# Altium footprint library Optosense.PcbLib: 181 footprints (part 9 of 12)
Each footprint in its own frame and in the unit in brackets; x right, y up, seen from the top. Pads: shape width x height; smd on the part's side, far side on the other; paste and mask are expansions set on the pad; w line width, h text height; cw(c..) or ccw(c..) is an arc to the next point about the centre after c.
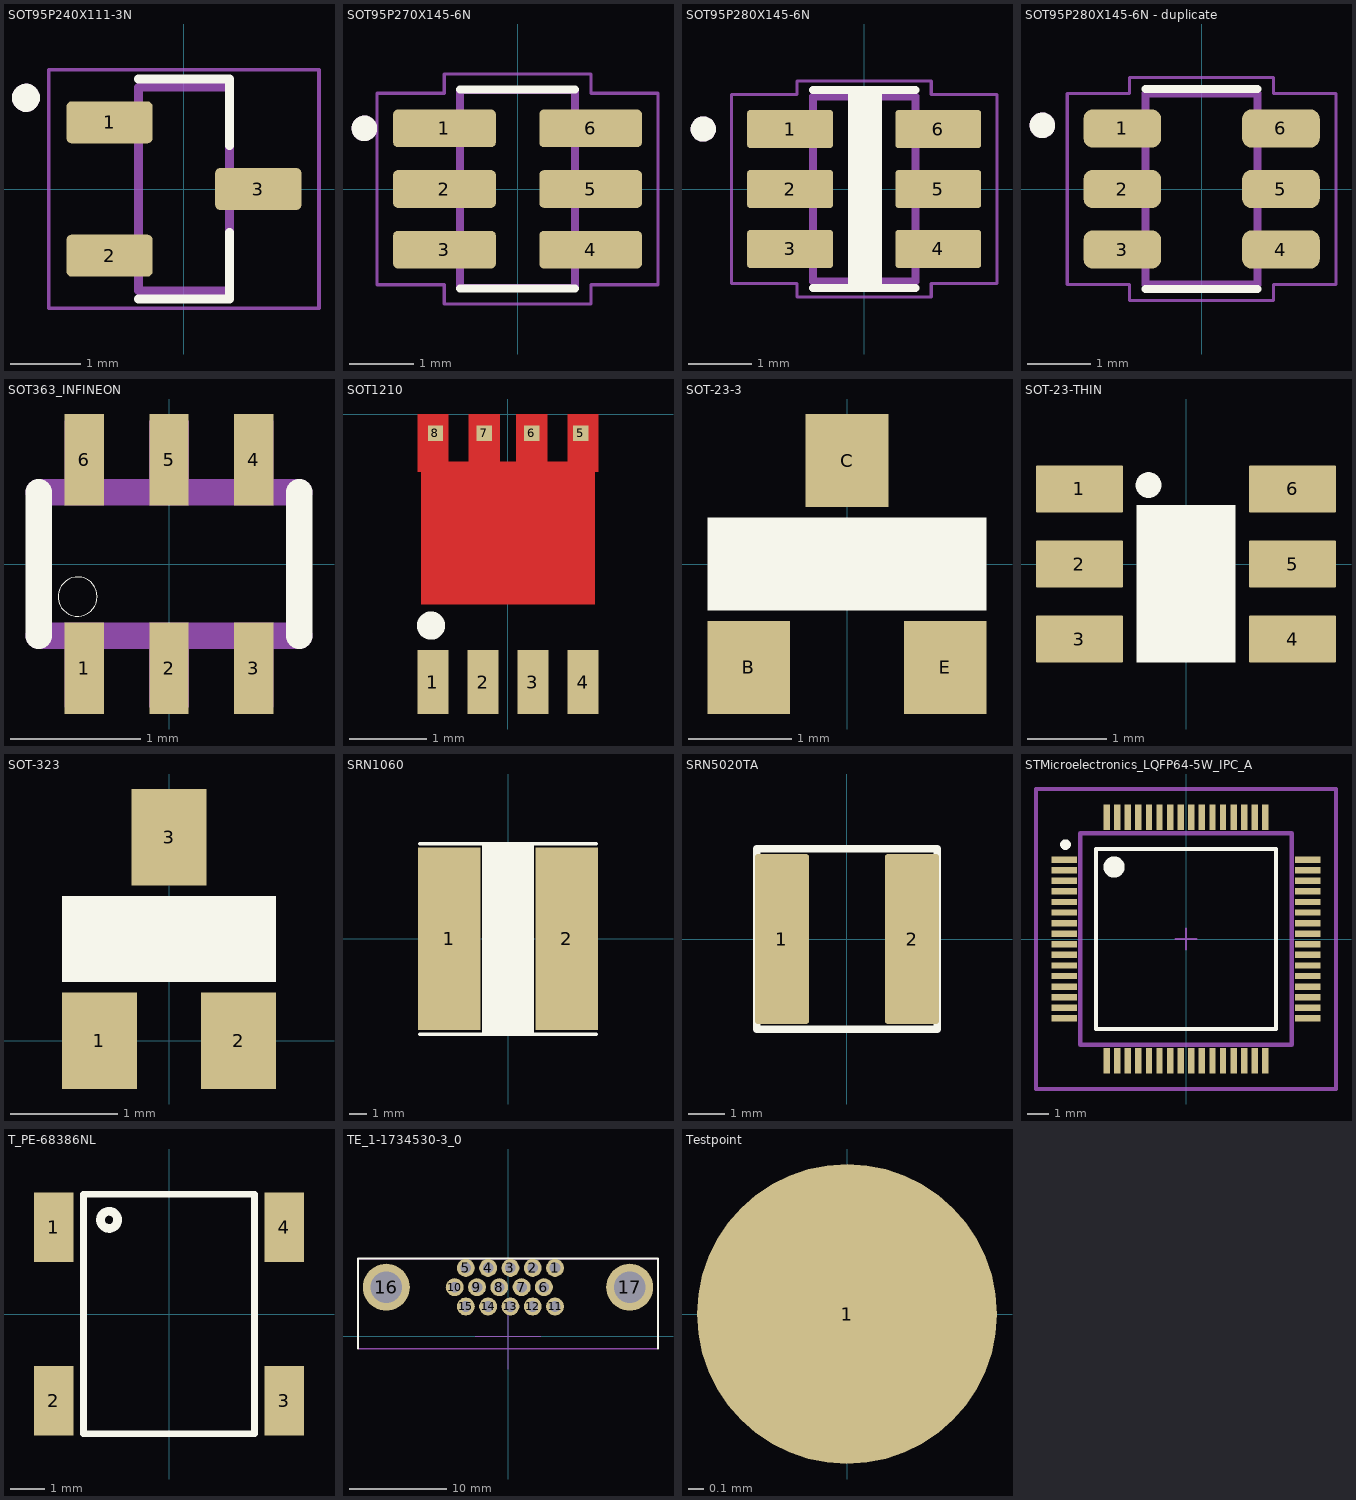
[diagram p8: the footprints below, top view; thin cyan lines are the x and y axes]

## SOT95P240X111-3N [mm]
pads (3):
  rrect25% 1.23x0.6 smd: 1(-1.06,0.95) 2(-1.06,-0.95) 3(1.06,0)
Top Overlay:
  circle w0.2: c-2.25,1.3 r0.1
  lines w0.127: -0.65,-1.57 0.65,-1.57 0.65,-0.62 ; -0.65,1.57 0.65,1.57 0.65,0.62
Mechanical 13:
  circle w0.2: c-2.25,1.3 r0.1
  lines w0.127: -0.65,-1.45 -0.65,1.45 0.65,1.45 0.65,-1.45 -0.65,-1.45
Mechanical 15:
  lines w0.05: -1.925,-1.7 1.925,-1.7 1.925,1.7 -1.925,1.7 -1.925,-1.7
3D body "step_temp.STEP": height 1.1, standoff 0, extent -1.15,-1.45 1.15,1.45

## SOT95P270X145-6N [mm]
pads (6):
  rrect25% 1.61x0.59 smd: 1(-1.145,0.95) 2(-1.145,0) 3(-1.145,-0.95) 4(1.145,-0.95) 5(1.145,0) 6(1.145,0.95)
Top Overlay:
  circle w0.2: c-2.4,0.95 r0.1
  lines w0.127: -0.9,-1.559 0.9,-1.559 ; -0.9,1.559 0.9,1.559
Mechanical 13:
  circle w0.2: c-2.4,0.95 r0.1
  lines w0.127: -0.9,-1.55 -0.9,1.55 0.9,1.55 0.9,-1.55 -0.9,-1.55
Mechanical 15:
  lines w0.05: -2.2,-1.5 -2.2,1.5 -1.15,1.5 -1.15,1.8 1.15,1.8 1.15,1.5 2.2,1.5 2.2,-1.5 1.15,-1.5 1.15,-1.8 -1.15,-1.8 -1.15,-1.5 -2.2,-1.5
3D body "USBLC6-2SC6Y--3DModel-STEP-56544.STEP": height 1.5, standoff 0.05, extent -1.43,-1.462 1.37,1.462

## SOT95P280X145-6N [mm]
pads (6):
  rrect15% 1.36x0.6 smd: 1(-1.175,0.95) 2(-1.175,0) 3(-1.175,-0.95) 4(1.175,-0.95) 5(1.175,0) 6(1.175,0.95)
Top Overlay:
  circle w0.2: c-2.55,0.95 r0.1
  rectangle: -0.254,-1.57 0.279,1.57
  lines w0.127: -0.813,-1.57 0.813,-1.57 ; -0.813,1.57 0.813,1.57
Mechanical 13:
  circle w0.2: c-2.55,0.95 r0.1
  lines w0.127: -0.813,-1.462 0.813,-1.462 0.813,1.462 -0.813,1.462 -0.813,-1.462
Mechanical 15:
  lines w0.05: -2.105,-1.5 -1.062,-1.5 -1.062,-1.713 1.062,-1.713 1.062,-1.5 2.105,-1.5 2.105,1.5 1.062,1.5 1.062,1.713 -1.062,1.713 -1.062,1.5 -2.105,1.5 -2.105,-1.5
3D body "USBLC6-2SC6Y--3DModel-STEP-56544.STEP": height 1.5, standoff 0.05, extent -1.4,-1.462 1.4,1.462

## SOT95P280X145-6N - duplicate [mm]
pads (6):
  rrect50% 1.22x0.6 smd: 1(-1.245,0.95) 2(-1.245,0) 3(-1.245,-0.95) 4(1.245,-0.95) 5(1.245,0) 6(1.245,0.95)
Top Overlay:
  circle w0.2: c-2.5,1 r0.1
  lines w0.127: -0.88,-1.57 0.88,-1.57 ; -0.88,1.57 0.88,1.57
Mechanical 13:
  circle w0.2: c-2.5,1 r0.1
  lines w0.127: -0.88,-1.5 0.88,-1.5 0.88,1.5 -0.88,1.5 -0.88,-1.5
Mechanical 15:
  lines w0.05: -2.11,-1.5 -2.11,1.5 -1.13,1.5 -1.13,1.75 1.13,1.75 1.13,1.5 2.11,1.5 2.11,-1.5 1.13,-1.5 1.13,-1.75 -1.13,-1.75 -1.13,-1.5 -2.11,-1.5

## SOT363_INFINEON [mm]
pads (6):
  rect 0.3x0.7 smd: 1(-0.65,-0.8) 2(0,-0.8) 3(0.65,-0.8) 4(0.65,0.8) 5(0,0.8) 6(-0.65,0.8)
Top Overlay:
  circle w0: c-0.7,-0.25 r0.15
  lines w0.203: -1,-0.55 -1,0.55 ; 1,-0.55 1,0.55
Mechanical 13:
  region: -0.5,0.6 -0.8,0.6 -0.8,1.1 -0.5,1.1
  region: 0.15,0.6 -0.15,0.6 -0.15,1.1 0.15,1.1
  region: 0.8,0.6 0.5,0.6 0.5,1.1 0.8,1.1
  region: 0.8,-1.1 0.5,-1.1 0.5,-0.6 0.8,-0.6
  region: 0.15,-1.1 -0.15,-1.1 -0.15,-0.6 0.15,-0.6
  region: -0.5,-1.1 -0.8,-1.1 -0.8,-0.6 -0.5,-0.6
  lines w0.203: -1,-0.55 1,-0.55 ; -1,0.55 1,0.55
3D body "User Library-sot363.STEP": height 1, standoff 0, extent -1.05,-1.15 1.05,1.15

## SOT1210 [mm]
pads (8):
  rect 0.4x0.83 smd: 1(-0.975,-3.485) 2(-0.325,-3.485) 3(0.325,-3.485) 4(0.975,-3.485)
  rect 0.2x0.2 smd: 5(0.944,-0.25) 6(0.309,-0.25) 7(-0.308,-0.25) 8(-0.943,-0.25)
Top Layer:
  region: -1.175,0 -1.175,-0.75 -1.125,-0.75 -1.125,-2.47 1.125,-2.47 1.125,-0.75 1.175,-0.75 1.175,0 0.775,0 0.775,-0.62 0.509,-0.62 0.509,0 0.109,0 0.109,-0.62 -0.109,-0.62 -0.109,0 -0.509,0 -0.509,-0.62 -0.775,-0.62 -0.775,0
Top Overlay:
  circle w0.254: c-1,-2.75 r0.056
Top Paste:
  region: -0.309,-1.91 -0.309,-2.42 -0.944,-2.42 -0.944,-1.91
  region: -1.125,0 -1.125,-0.75 -0.825,-0.75 -0.825,0
  region: -0.459,0 -0.459,-0.75 -0.159,-0.75 -0.159,0
  region: 0.159,0 0.159,-0.75 0.459,-0.75 0.459,0
  region: 1.125,0 1.125,-0.75 0.825,-0.75 0.825,0
  region: -0.309,-1.05 -0.309,-1.56 -0.944,-1.56 -0.944,-1.05
  region: 0.943,-1.05 0.943,-1.56 0.308,-1.56 0.308,-1.05
  region: 0.943,-1.91 0.943,-2.42 0.308,-2.42 0.308,-1.91
3D body "SOT1210.step": height 0.61, standoff -0.25, extent -1.638,-3.512 1.662,-0.212

## SOT-23-3 [mm]
height 1.025
pads (3):
  rect 0.8x0.9 smd: B(-0.95,-1) C(0,1) E(0.95,-1)
Top Overlay:
  rectangle: -1.35,-0.45 1.35,0.45
3D body "User Library-3-lead sot23-3.STEP": height 1, standoff -0.02, extent -1.46,-1.225 1.46,1.251

## SOT-23-THIN [mm]
height 1.1
pads (6):
  rrect5% 1.1x0.6 smd mask+0.07: 1(-1.35,0.95) 2(-1.35,0) 3(-1.35,-0.95) 4(1.35,-0.95) 5(1.35,0) 6(1.35,0.95)
Top Overlay:
  circle w0.254: c-0.475,1 r0.035
  rectangle: -0.625,-1.25 0.625,0.75
3D body "TPS54302DDCT.stp": height 1.1, standoff 0, extent -1.4,-1.45 1.4,1.45

## SOT-323 [mm]
height 1.1
pads (3):
  rect 0.7x0.9 smd: 1(-0.65,0) 2(0.65,0) 3(0,1.9)
Top Overlay:
  rectangle: -1,0.55 1,1.35
3D body "User Library-BC847BW.step": height 0.3, standoff -0.65, extent -1,-0.05 1,2.05

## Splitter [mm]
3D body "Splitter.step": height 26.51, standoff 0.6, extent -3.5,0 105.597,80

## SRN1060 [mm]
height 6
pads (2):
  rect 3.5x10.2 smd paste-5: 1(-3.3,0) 2(3.3,0)
Top Overlay:
  rectangle: -1.45,-5.35 1.45,5.325
  lines w0.2: -4.95,-5.35 4.95,-5.35 ; -4.95,5.325 4.95,5.325
Top Paste:
  rectangle: 2,-5 4.5,-3.5
  rectangle: 2,-3 4.5,-1.5
  rectangle: 2,-0.75 4.5,0.75
  rectangle: 2,1.5 4.5,3
  rectangle: 2,3.5 4.5,5
  rectangle: -4.5,-5 -2,-3.5
  rectangle: -4.5,-3 -2,-1.5
  rectangle: -4.5,-0.75 -2,0.75
  rectangle: -4.5,1.5 -2,3
  rectangle: -4.5,3.5 -2,5
3D body "WE-TPC_1038 (rev1).stp": height 3.8, standoff 0, extent -5,-5 5,5

## SRN5020TA [mm]
height 1.8
pads (2):
  rrect10% 1.5x4.7 smd: 1(-1.8,0) 2(1.8,0)
Top Overlay:
  lines w0.2: -2.5,-2.5 2.5,-2.5 2.5,2.5 -2.5,2.5 -2.5,-2.5

## STMicroelectronics_LQFP64-5W_IPC_A [mm]
pads (64):
  rect 1.2x0.3 smd paste+0 mask+0: 1(-5.75,3.75) 2(-5.75,3.25) 3(-5.75,2.75) 4(-5.75,2.25) 5(-5.75,1.75) 6(-5.75,1.25) 7(-5.75,0.75) 8(-5.75,0.25) 9(-5.75,-0.25) 10(-5.75,-0.75) 11(-5.75,-1.25) 12(-5.75,-1.75) 13(-5.75,-2.25) 14(-5.75,-2.75) 15(-5.75,-3.25) 16(-5.75,-3.75) 33(5.75,-3.75) 34(5.75,-3.25) 35(5.75,-2.75) 36(5.75,-2.25) 37(5.75,-1.75) 38(5.75,-1.25) 39(5.75,-0.75) 40(5.75,-0.25) 41(5.75,0.25) 42(5.75,0.75) 43(5.75,1.25) 44(5.75,1.75) 45(5.75,2.25) 46(5.75,2.75) 47(5.75,3.25) 48(5.75,3.75)
  rect 0.3x1.2 smd paste+0 mask+0: 17(-3.75,-5.75) 18(-3.25,-5.75) 19(-2.75,-5.75) 20(-2.25,-5.75) 21(-1.75,-5.75) 22(-1.25,-5.75) 23(-0.75,-5.75) 24(-0.25,-5.75) 25(0.25,-5.75) 26(0.75,-5.75) 27(1.25,-5.75) 28(1.75,-5.75) 29(2.25,-5.75) 30(2.75,-5.75) 31(3.25,-5.75) 32(3.75,-5.75) 49(3.75,5.75) 50(3.25,5.75) 51(2.75,5.75) 52(2.25,5.75) 53(1.75,5.75) 54(1.25,5.75) 55(0.75,5.75) 56(0.25,5.75) 57(-0.25,5.75) 58(-0.75,5.75) 59(-1.25,5.75) 60(-1.75,5.75) 61(-2.25,5.75) 62(-2.75,5.75) 63(-3.25,5.75) 64(-3.75,5.75)
Top Overlay:
  circle w0.25: c-5.691,4.46 r0.125
  circle w0.5: c-3.4,3.4 r0.25
  lines w0.2: -4.25,-4.25 4.25,-4.25 4.25,4.25 -4.25,4.25 -4.25,-4.25
Mechanical 10:
  lines w0.2: -7.085,-7.085 7.085,-7.085 7.085,7.085 -7.085,7.085 -7.085,-7.085
  text ".Designator" at 0,0 h1
Mechanical 12:
  lines w0.2: -5,-5 5,-5 5,5 -5,5 -5,-5
Mechanical 15:
  lines w0.1: -0.5,0 0.5,0 ; 0,-0.5 0,0.5
  lines w0.2: -7.085,-7.085 7.085,-7.085 7.085,7.085 -7.085,7.085 -7.085,-7.085
3D body "IC_STMicroelectronics_STM32G474RET6_eec.STEP": height 0.25, standoff 0, extent -7.085,-7.085 7.085,7.085

## T_PE-68386NL [mil]
pads (4):
  rect 45x80 smd: 1(-132.5,100) 2(-132.5,-100) 3(132.5,-100) 4(132.5,100)
Top Overlay:
  circle w10: c-68.9,108.27 r9.84
  lines w7.87: -98.43,-137.8 -98.43,137.8 98.43,137.8 98.43,-137.8 -98.43,-137.8
3D body "PE-68386NL--3DModel-Eagle-1.STEP": height 97.87, standoff -0.13, extent -170,-132.49 170,132.51

## TE_1-1734530-3_0 [mm]
pads (17):
  round 1.84 hole 1.09 paste-1000 mask+0: 1(4.83,7.04) 2(2.54,7.04) 3(0.25,7.04) 4(-2.04,7.04) 5(-4.33,7.04) 6(3.685,5.06) 7(1.395,5.06) 8(-0.895,5.06) 9(-3.185,5.06) 10(-5.475,5.06) 11(4.83,3.08) 12(2.54,3.08) 13(0.25,3.08) 14(-2.04,3.08) 15(-4.33,3.08)
  round 4.83 hole 3.2 paste-1000 mask+0: 16(-12.495,5.06) 17(12.495,5.06)
Top Overlay:
  lines w0.2: -15.4,-1.25 -15.4,8 15.4,8 15.4,-1.25
Mechanical 10:
  text ".Designator" at 0,0 h1
Mechanical 12:
  lines w0.152: -15.4,-1.25 15.4,-1.25 15.4,8 -15.4,8 -15.4,-1.25
Mechanical 15:
  lines w0.1: -3.387,0 3.387,0 ; 0,-3.387 0,3.387
3D body "VGA connector on plate (short).STEP": height 3.49, standoff -12.98, extent -15.4,-6.9 15.4,8

## Testpoint [mm]
pads (1):
  round 2 smd paste+0 mask+0: 1(0,0)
